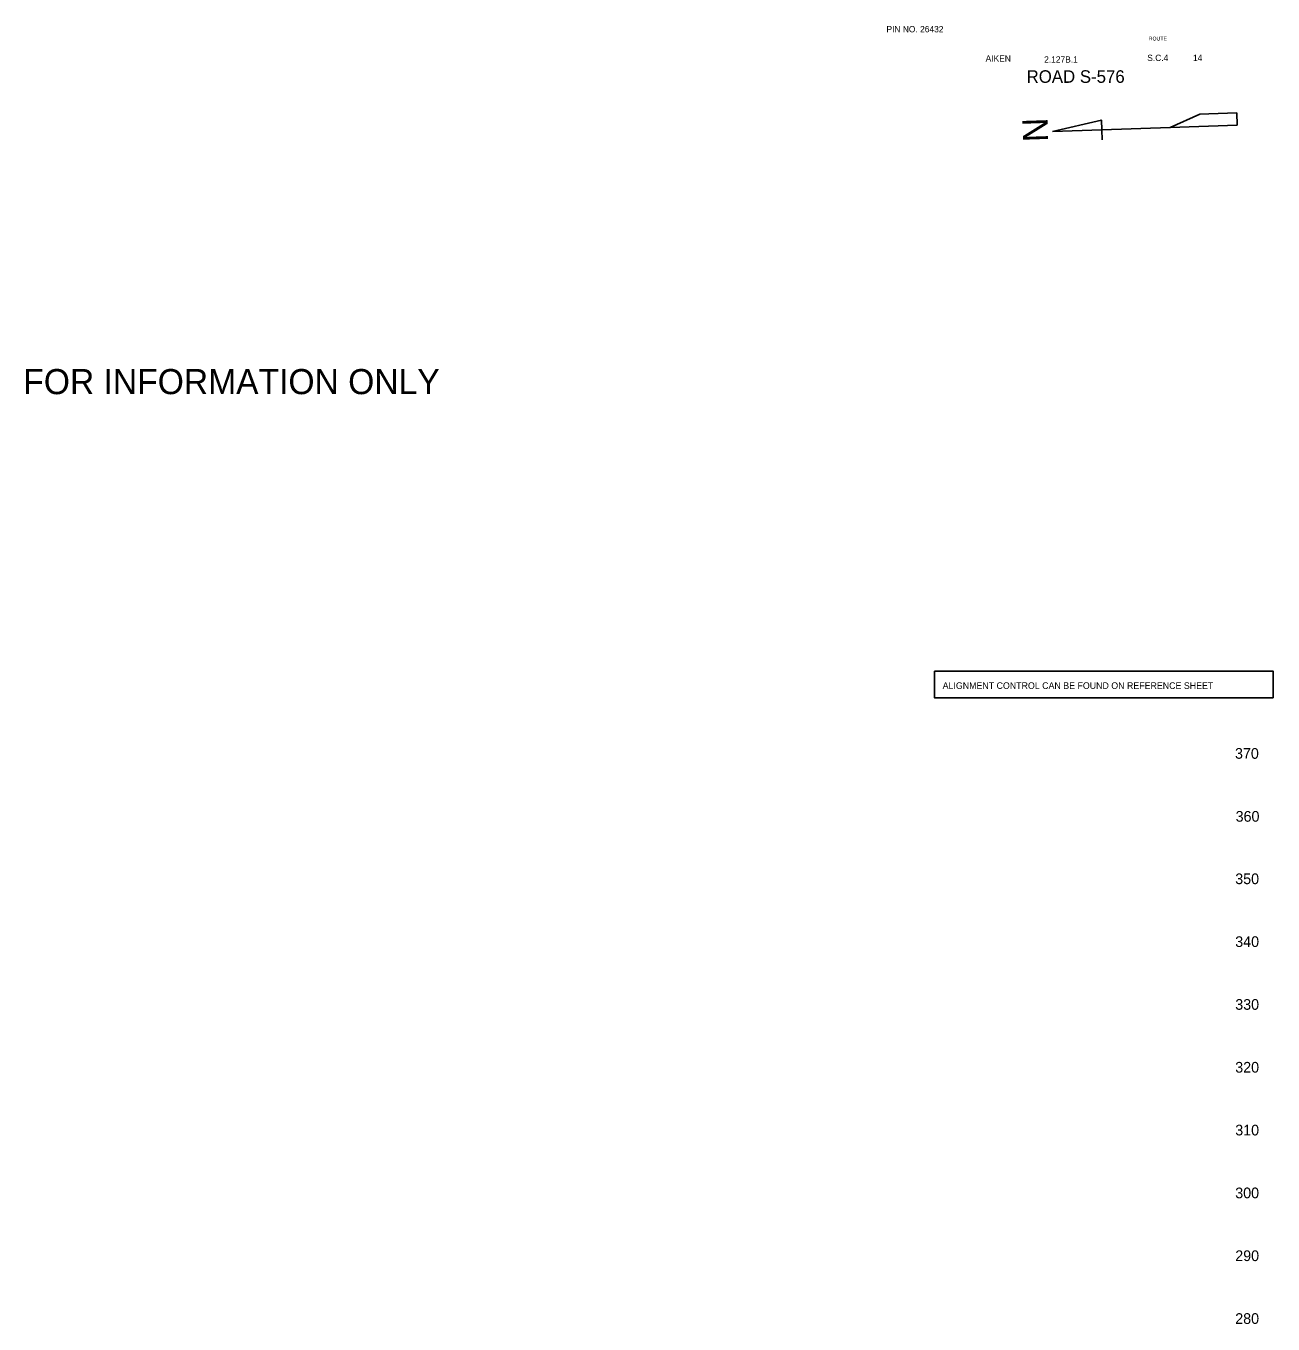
# Model space of a CAD drawing. Extents: x 51331 to 53000, y 49946 to 50990.
# Drawn here: x 52007 to 53000, y 49957 to 50990 of the extents above; entities that cross this region are included whole.
import ezdxf

# ---------------------------------------------------------------- set-up
doc = ezdxf.new("R2010")
doc.units = 0
for name, color, linetype in [('Level 1', 7, 'Continuous'), ('Level 2', 7, 'Continuous'), ('Level 24', 7, 'Continuous'), ('Level 25', 7, 'Continuous'), ('Level 33', 7, 'Continuous'), ('Level 42', 7, 'Continuous')]:
    doc.layers.add(name, color=color, linetype=linetype)

msp = doc.modelspace()

# ---------------------------------------------------------------- linework, layer by layer
at = {"layer": 'Level 2'}
for p, q in [((52941.3, 50919.5), (52917.7, 50908.9)), ((52970.7, 50920.5), (52941.1, 50919.5)), ((52941.1, 50919.5), (52941.3, 50919.5)), ((52971.1, 50910.7), (52970.7, 50920.5)), ((52863, 50914.9), (52824.1, 50905.7)), ((52824.1, 50905.7), (52863.3, 50907.1)), ((52824.1, 50905.7), (52824.1, 50905.7)), ((52863, 50914.9), (52862.6, 50914.9)), ((52863.3, 50907.1), (52863, 50914.9)), ((52917.7, 50908.9), (52863.3, 50907.1)), ((52863.6, 50899.2), (52863.3, 50907.1)), ((52917.7, 50908.9), (52971.1, 50910.7))]:
    msp.add_line(p, q, dxfattribs=at)
at = {"layer": 'Level 25'}
msp.add_lwpolyline([(52730.2, 50476.3), (52999.6, 50476.3), (52999.6, 50455), (52730.2, 50455)], close=True, dxfattribs=at)

# ---------------------------------------------------------------- texts
at = {"layer": 'Level 1'}
msp.add_text('ROUTE', height=3, dxfattribs=at).set_placement((52900.7, 50978.2))
at = {"layer": 'Level 2'}
msp.add_text('N', height=20, rotation=91.949, dxfattribs=at).set_placement((52820.7, 50897.7))
at = {"layer": 'Level 24'}
for s, height, p in [('PIN NO. 26432', 5, (52692, 50984.7)), ('AIKEN', 5, (52770.9, 50961.4)), (' 2.127B.1', 5, (52815.6, 50960.6)), ('S.C.4', 5, (52899.5, 50961.9)), ('14', 5, (52935.9, 50961.9)), ('ROAD S-576', 10, (52803.5, 50944.5))]:
    msp.add_text(s, height=height, dxfattribs=at).set_placement(p)
at = {"layer": 'Level 25'}
msp.add_text('ALIGNMENT CONTROL CAN BE FOUND ON REFERENCE SHEET', height=5.25, dxfattribs=at).set_placement((52736.7, 50462.1))
at = {"layer": 'Level 33'}
msp.add_text('FOR INFORMATION ONLY', height=20, dxfattribs=at).set_placement((52005.2, 50696.7))
at = {"layer": 'Level 42'}
for s, p in [('370', (52969.3, 50406.5)), ('360', (52969.8, 50356.4)), ('350', (52969.5, 50306.7)), ('340', (52969.5, 50256.7)), ('330', (52969.5, 50206.7)), ('320', (52969.5, 50156.7)), ('310', (52969.5, 50106.7)), ('300', (52969.5, 50056.7)), ('290', (52969.5, 50006.7)), ('280', (52969.5, 49956.7))]:
    msp.add_text(s, height=8.5, dxfattribs=at).set_placement(p)

doc.saveas('drawing.dxf')
